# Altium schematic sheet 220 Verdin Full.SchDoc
size A3; Organization: Toradex Solutions Inc.; Address1: 6415 Northwest Drive; Address2: Mississauga, ON, L4V 1X1; Address3: Canada
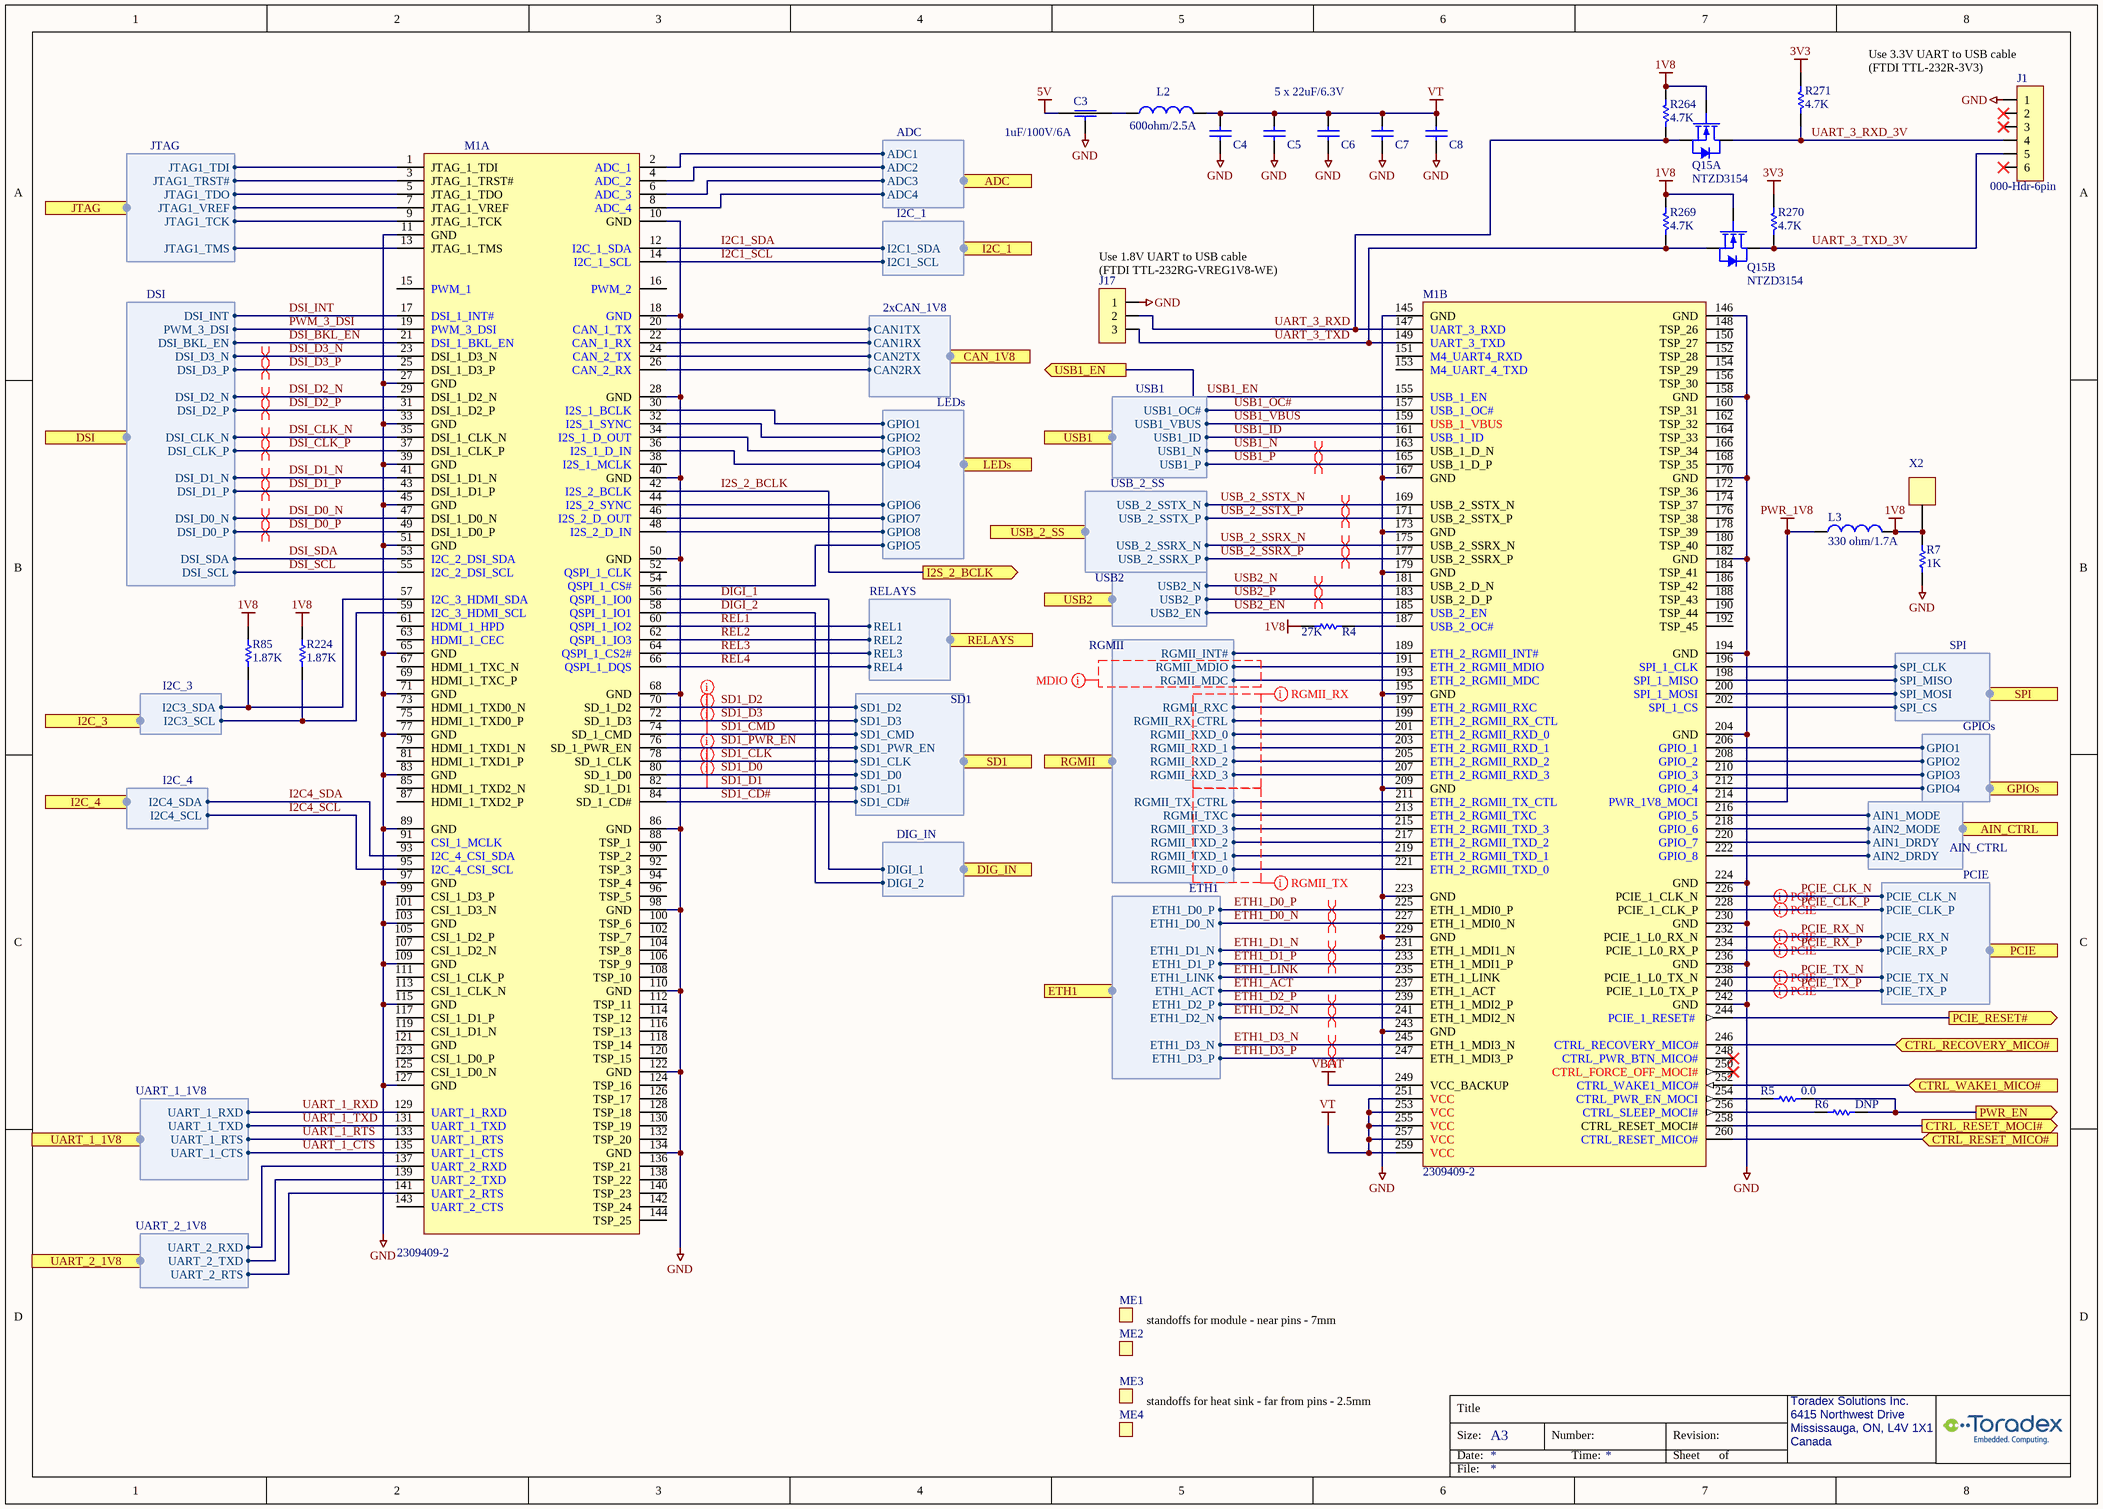
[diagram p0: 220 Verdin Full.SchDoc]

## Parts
C3  value 1uF/100V/6A  [C/1206_3P]  (hidden comment: 0753-Cap 3P-1206-1uF/100V/6A)
C4  22uF/6.3V  [C0402_CAPC1005L]  (value not drawn)
C5  22uF/6.3V  [C0402_CAPC1005L]  (value not drawn)
C6  22uF/6.3V  [C0402_CAPC1005L]  (value not drawn)
C7  22uF/6.3V  [C0402_CAPC1005L]  (value not drawn)
C8  22uF/6.3V  [C0402_CAPC1005L]  (value not drawn)
J1  000-Hdr-6pin  [HDR1X6]
J17  000-Hdr-3pin  [HDR1X3]  (value not drawn)
L2  value 600ohm/2.5A  [INDP1206]  (hidden comment: 1641-Fer-1206-600ohm/2.5A)
L3  value 330 ohm/1.7A  [INDC1608x095]  (hidden comment: 0405-Fer-0603-330ohm/1.7A)
M1  2309409-2  [CON-TE-2309409-2_TORADEX_VERDIN_MTG_rev2]  (parts A,B of 2)
ME1  9774070243R  [MTG_POST WURTH 774070243]  (value not drawn)
ME2  9774070243R  [MTG_POST WURTH 774070243]  (value not drawn)
ME3  9774025243R  [WURTH_9774025243R]  (value not drawn)
ME4  9774025243R  [WURTH_9774025243R]  (value not drawn)
Q15  NTZD3154  [SOT563]  (parts A,B of 2)
R4  value 27K  [R0402_RESC1005L]  (hidden comment: 1538-Res-0402-27k)
R5  value 0.0  [R/0603]  (hidden comment: 0195-Res-0603-0.0ohm)
R6  value DNP  [R/0603]  (hidden comment: 0000-Res-0603-DNP)
R7  value 1K  [R0402_RESC1005L]  (hidden comment: 1650-Res-0402-1K)
R85  value 1.87K  [R0402_RESC1005L]  (hidden comment: 1536-Res-0402-1.87K)
R224  value 1.87K  [R0402_RESC1005L]  (hidden comment: 1536-Res-0402-1.87K)
R264  value 4.7K  [R0402_RESC1005L]  (hidden comment: 2233-Res-0402-4.7K)
R269  value 4.7K  [R0402_RESC1005L]  (hidden comment: 2233-Res-0402-4.7K)
R270  value 4.7K  [R0402_RESC1005L]  (hidden comment: 2233-Res-0402-4.7K)
R271  value 4.7K  [R0402_RESC1005L]  (hidden comment: 2233-Res-0402-4.7K)
X2  000-TestPoint  [TestPoint_1]  (value not drawn)

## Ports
ADC (harness ADC), AIN_CTRL (harness AIN_CTRL), CAN_1V8 (harness 2xCAN_1V8), CTRL_RECOVERY_MICO# (in), CTRL_RESET_MICO# (in), CTRL_RESET_MOCI# (out), CTRL_WAKE1_MICO# (in), DIG_IN (harness DIG_IN), DSI (harness DSI), ETH1 (harness ETH1), GPIOs (harness GPIOs), I2C_1 (harness I2C_1), I2C_3 (harness I2C_3), I2C_4 (harness I2C_4), I2S_2_BCLK (out), JTAG (harness JTAG), LEDs (harness LEDs), PCIE (harness PCIe), PCIE_RESET# (out), PWR_EN (out), RELAYS (harness RELAYS), RGMII (harness RGMII), SD1 (harness SD1), SPI (harness SPI), UART_1_1V8 (harness UART_1_1V8), UART_2_1V8 (harness UART_2_1V8), USB1 (harness USB1), USB1_EN (out), USB2 (harness USB2), USB_2_SS (harness USB_2_SS)

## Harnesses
ETH1: ETH1_D0_P, ETH1_D0_N, ETH1_D1_N, ETH1_D1_P, ETH1_LINK, ETH1_ACT, ETH1_D2_P, ETH1_D2_N, ETH1_D3_N, ETH1_D3_P
USB2: USB2_N, USB2_P, USB2_EN
USB1: USB1_N, USB1_P, USB1_ID, USB1_VBUS, USB1_OC#
PCIE: PCIE_CLK_N, PCIE_CLK_P, PCIE_RX_N, PCIE_RX_P, PCIE_TX_N, PCIE_TX_P
SPI: SPI_CLK, SPI_MISO, SPI_MOSI, SPI_CS
AIN_CTRL: AIN1_MODE, AIN2_MODE, AIN1_DRDY, AIN2_DRDY
GPIOs: GPIO1, GPIO2, GPIO3, GPIO4
RGMII: RGMII_TXD_0, RGMII_TXD_1, RGMII_TXD_2, RGMII_TXD_3, RGMII_TXC, RGMII_TX_CTRL, RGMII_RXD_0, RGMII_RXD_1, RGMII_RXD_2, RGMII_RXD_3, RGMII_RXC, RGMII_RX_CTRL, RGMII_MDIO, RGMII_MDC, RGMII_INT#
SD1: SD1_D2, SD1_D3, SD1_CMD, SD1_PWR_EN, SD1_CLK, SD1_D0, SD1_D1, SD1_CD#
2xCAN_1V8: CAN1TX, CAN1RX, CAN2TX, CAN2RX
UART_1_1V8: UART_1_RXD, UART_1_TXD, UART_1_RTS, UART_1_CTS
UART_2_1V8: UART_2_RXD, UART_2_TXD, UART_2_RTS
RELAYS: REL1, REL2, REL3, REL4
I2C_1: I2C1_SDA, I2C1_SCL
DIG_IN: DIGI_1, DIGI_2
JTAG: JTAG1_TDI, JTAG1_TRST#, JTAG1_TDO, JTAG1_VREF, JTAG1_TCK, JTAG1_TMS
LEDs: GPIO1, GPIO2, GPIO3, GPIO4, GPIO7, GPIO8, GPIO6, GPIO5
I2C_4: I2C4_SDA, I2C4_SCL
DSI: DSI_SDA, DSI_SCL, DSI_BKL_EN, PWM_3_DSI, DSI_INT, DSI_D3_N, DSI_D3_P, DSI_D2_N, DSI_D2_P, DSI_CLK_N, DSI_CLK_P, DSI_D1_N, DSI_D1_P, DSI_D0_N, DSI_D0_P
ADC: ADC1, ADC2, ADC3, ADC4
I2C_3: I2C3_SDA, I2C3_SCL
USB_2_SS: USB_2_SSTX_N, USB_2_SSTX_P, USB_2_SSRX_N, USB_2_SSRX_P

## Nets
1V8: L3.1 Q15.2(G) Q15.5(G) R4.1 R7.2 R85.2 R224.2 R264.1 R269.1 X2.1
3V3: R270.1 R271.1
5V: C3.1(In/Out)
GND: C3.2(Gnd) C4.1 C5.1 C6.1 C7.1 C8.1 J1.1 J17.1 M1.10(GND) M1.11(GND) M1.18(GND) M1.27(GND) M1.28(GND) M1.33(GND) M1.39(GND) M1.40(GND) M1.45(GND) M1.50(GND) M1.51(GND) M1.65(GND) M1.68(GND) M1.71(GND) M1.77(GND) M1.83(GND) M1.86(GND) M1.89(GND) M1.97(GND) M1.98(GND) M1.103(GND) M1.109(GND) M1.110(GND) M1.115(GND) M1.122(GND) M1.127(GND) M1.134(GND) M1.145(GND) M1.146(GND) M1.158(GND) M1.167(GND) M1.170(GND) M1.173(GND) M1.179(GND) M1.182(GND) M1.194(GND) M1.195(GND) M1.204(GND) M1.209(GND) M1.223(GND) M1.224(GND) M1.229(GND) M1.230(GND) M1.236(GND) M1.242(GND) M1.243(GND) R7.1
PWR_1V8: L3.2 M1.214(PWR_1V8_MOCI)
VBAT: M1.249(VCC_BACKUP)
VT: C4.2 C5.2 C6.2 C7.2 C8.2 L2.2 M1.251(VCC) M1.253(VCC) M1.255(VCC) M1.257(VCC) M1.259(VCC)
CTRL_RECOVERY_MICO#: M1.246(CTRL_RECOVERY_MICO#) ; port CTRL_RECOVERY_MICO#
CTRL_RESET_MICO#: M1.260(CTRL_RESET_MICO#) ; port CTRL_RESET_MICO#
CTRL_RESET_MOCI#: M1.258(CTRL_RESET_MOCI#) ; port CTRL_RESET_MOCI#
CTRL_WAKE1_MICO#: M1.252(CTRL_WAKE1_MICO#) ; port CTRL_WAKE1_MICO#
DIGI_1: M1.56(QSPI_1_IO0) ; port DIG_IN.DIGI_1
DIGI_2: M1.58(QSPI_1_IO1) ; port DIG_IN.DIGI_2
DSI_BKL_EN: M1.21(DSI_1_BKL_EN) ; port DSI.DSI_BKL_EN
DSI_CLK_N: M1.35(DSI_1_CLK_N) ; port DSI.DSI_CLK_N
DSI_CLK_P: M1.37(DSI_1_CLK_P) ; port DSI.DSI_CLK_P
DSI_D0_N: M1.47(DSI_1_D0_N) ; port DSI.DSI_D0_N
DSI_D0_P: M1.49(DSI_1_D0_P) ; port DSI.DSI_D0_P
DSI_D1_N: M1.41(DSI_1_D1_N) ; port DSI.DSI_D1_N
DSI_D1_P: M1.43(DSI_1_D1_P) ; port DSI.DSI_D1_P
DSI_D2_N: M1.29(DSI_1_D2_N) ; port DSI.DSI_D2_N
DSI_D2_P: M1.31(DSI_1_D2_P) ; port DSI.DSI_D2_P
DSI_D3_N: M1.23(DSI_1_D3_N) ; port DSI.DSI_D3_N
DSI_D3_P: M1.25(DSI_1_D3_P) ; port DSI.DSI_D3_P
DSI_INT: M1.17(DSI_1_INT#) ; port DSI.DSI_INT
DSI_SCL: M1.55(I2C_2_DSI_SCL) ; port DSI.DSI_SCL
DSI_SDA: M1.53(I2C_2_DSI_SDA) ; port DSI.DSI_SDA
ETH1_ACT: M1.237(ETH_1_ACT) ; port ETH1.ETH1_ACT
ETH1_D0_N: M1.227(ETH_1_MDI0_N) ; port ETH1.ETH1_D0_N
ETH1_D0_P: M1.225(ETH_1_MDI0_P) ; port ETH1.ETH1_D0_P
ETH1_D1_N: M1.231(ETH_1_MDI1_N) ; port ETH1.ETH1_D1_N
ETH1_D1_P: M1.233(ETH_1_MDI1_P) ; port ETH1.ETH1_D1_P
ETH1_D2_N: M1.241(ETH_1_MDI2_N) ; port ETH1.ETH1_D2_N
ETH1_D2_P: M1.239(ETH_1_MDI2_P) ; port ETH1.ETH1_D2_P
ETH1_D3_N: M1.245(ETH_1_MDI3_N) ; port ETH1.ETH1_D3_N
ETH1_D3_P: M1.247(ETH_1_MDI3_P) ; port ETH1.ETH1_D3_P
ETH1_LINK: M1.235(ETH_1_LINK) ; port ETH1.ETH1_LINK
I2C1_SCL: M1.14(I2C_1_SCL) ; port I2C_1.I2C1_SCL
I2C1_SDA: M1.12(I2C_1_SDA) ; port I2C_1.I2C1_SDA
I2C4_SCL: M1.95(I2C_4_CSI_SCL) ; port I2C_4.I2C4_SCL
I2C4_SDA: M1.93(I2C_4_CSI_SDA) ; port I2C_4.I2C4_SDA
I2S_2_BCLK: M1.42(I2S_2_BCLK) ; port I2S_2_BCLK
PCIE_CLK_N: M1.226(PCIE_1_CLK_N) ; port PCIE.PCIE_CLK_N
PCIE_CLK_P: M1.228(PCIE_1_CLK_P) ; port PCIE.PCIE_CLK_P
PCIE_RESET#: M1.244(PCIE_1_RESET#) ; port PCIE_RESET#
PCIE_RX_N: M1.232(PCIE_1_L0_RX_N) ; port PCIE.PCIE_RX_N
PCIE_RX_P: M1.234(PCIE_1_L0_RX_P) ; port PCIE.PCIE_RX_P
PCIE_TX_N: M1.238(PCIE_1_L0_TX_N) ; port PCIE.PCIE_TX_N
PCIE_TX_P: M1.240(PCIE_1_L0_TX_P) ; port PCIE.PCIE_TX_P
PWM_3_DSI: M1.19(PWM_3_DSI) ; port DSI.PWM_3_DSI
PWR_EN: R5.1 R6.1 ; port PWR_EN
REL1: M1.60(QSPI_1_IO2) ; port RELAYS.REL1
REL2: M1.62(QSPI_1_IO3) ; port RELAYS.REL2
REL3: M1.64(QSPI_1_CS2#) ; port RELAYS.REL3
REL4: M1.66(QSPI_1_DQS) ; port RELAYS.REL4
SD1_CD#: M1.84(SD_1_CD#) ; port SD1.SD1_CD#
SD1_CLK: M1.78(SD_1_CLK) ; port SD1.SD1_CLK
SD1_CMD: M1.74(SD_1_CMD) ; port SD1.SD1_CMD
SD1_D0: M1.80(SD_1_D0) ; port SD1.SD1_D0
SD1_D1: M1.82(SD_1_D1) ; port SD1.SD1_D1
SD1_D2: M1.70(SD_1_D2) ; port SD1.SD1_D2
SD1_D3: M1.72(SD_1_D3) ; port SD1.SD1_D3
SD1_PWR_EN: M1.76(SD_1_PWR_EN) ; port SD1.SD1_PWR_EN
UART_1_CTS: M1.135(UART_1_CTS) ; port UART_1_1V8.UART_1_CTS
UART_1_RTS: M1.133(UART_1_RTS) ; port UART_1_1V8.UART_1_RTS
UART_1_RXD: M1.129(UART_1_RXD) ; port UART_1_1V8.UART_1_RXD
UART_1_TXD: M1.131(UART_1_TXD) ; port UART_1_1V8.UART_1_TXD
UART_3_RXD: J17.2 M1.147(UART_3_RXD) Q15.1(S) R264.2
UART_3_RXD_3V: J1.4 Q15.6(D) R271.2
UART_3_TXD: J17.3 M1.149(UART_3_TXD) Q15.4(S) R269.2
UART_3_TXD_3V: J1.5 Q15.3(D) R270.2
USB1_EN: M1.155(USB_1_EN) ; port USB1_EN
USB1_ID: M1.161(USB_1_ID) ; port USB1.USB1_ID
USB1_N: M1.163(USB_1_D_N) ; port USB1.USB1_N
USB1_OC#: M1.157(USB_1_OC#) ; port USB1.USB1_OC#
USB1_P: M1.165(USB_1_D_P) ; port USB1.USB1_P
USB1_VBUS: M1.159(USB_1_VBUS) ; port USB1.USB1_VBUS
USB2_EN: M1.185(USB_2_EN) ; port USB2.USB2_EN
USB2_N: M1.181(USB_2_D_N) ; port USB2.USB2_N
USB2_P: M1.183(USB_2_D_P) ; port USB2.USB2_P
USB_2_SSRX_N: M1.175(USB_2_SSRX_N) ; port USB_2_SS.USB_2_SSRX_N
USB_2_SSRX_P: M1.177(USB_2_SSRX_P) ; port USB_2_SS.USB_2_SSRX_P
USB_2_SSTX_N: M1.169(USB_2_SSTX_N) ; port USB_2_SS.USB_2_SSTX_N
USB_2_SSTX_P: M1.171(USB_2_SSTX_P) ; port USB_2_SS.USB_2_SSTX_P
NetC3_3: C3.3(In/Out) L2.1
NetM1_1: M1.1(JTAG_1_TDI) ; port JTAG.JTAG1_TDI
NetM1_2: M1.2(ADC_1) ; port ADC.ADC1
NetM1_3: M1.3(JTAG_1_TRST#) ; port JTAG.JTAG1_TRST#
NetM1_4: M1.4(ADC_2) ; port ADC.ADC2
NetM1_5: M1.5(JTAG_1_TDO) ; port JTAG.JTAG1_TDO
NetM1_6: M1.6(ADC_3) ; port ADC.ADC3
NetM1_7: M1.7(JTAG_1_VREF) ; port JTAG.JTAG1_VREF
NetM1_8: M1.8(ADC_4) ; port ADC.ADC4
NetM1_9: M1.9(JTAG_1_TCK) ; port JTAG.JTAG1_TCK
NetM1_13: M1.13(JTAG_1_TMS) ; port JTAG.JTAG1_TMS
NetM1_20: M1.20(CAN_1_TX) ; port CAN_1V8.CAN1TX
NetM1_22: M1.22(CAN_1_RX) ; port CAN_1V8.CAN1RX
NetM1_24: M1.24(CAN_2_TX) ; port CAN_1V8.CAN2TX
NetM1_26: M1.26(CAN_2_RX) ; port CAN_1V8.CAN2RX
NetM1_30: M1.30(I2S_1_BCLK) ; port LEDs.GPIO1
NetM1_32: M1.32(I2S_1_SYNC) ; port LEDs.GPIO2
NetM1_34: M1.34(I2S_1_D_OUT) ; port LEDs.GPIO3
NetM1_36: M1.36(I2S_1_D_IN) ; port LEDs.GPIO4
NetM1_44: M1.44(I2S_2_SYNC) ; port LEDs.GPIO6
NetM1_46: M1.46(I2S_2_D_OUT) ; port LEDs.GPIO7
NetM1_48: M1.48(I2S_2_D_IN) ; port LEDs.GPIO8
NetM1_54: M1.54(QSPI_1_CS#) ; port LEDs.GPIO5
NetM1_57: M1.57(I2C_3_HDMI_SDA) R85.1 ; port I2C_3.I2C3_SDA
NetM1_59: M1.59(I2C_3_HDMI_SCL) R224.1 ; port I2C_3.I2C3_SCL
NetM1_137: M1.137(UART_2_RXD) ; port UART_2_1V8.UART_2_RXD
NetM1_139: M1.139(UART_2_TXD) ; port UART_2_1V8.UART_2_TXD
NetM1_141: M1.141(UART_2_RTS) ; port UART_2_1V8.UART_2_RTS
NetM1_187: M1.187(USB_2_OC#) R4.2
NetM1_189: M1.189(ETH_2_RGMII_INT#) ; port RGMII.RGMII_INT#
NetM1_191: M1.191(ETH_2_RGMII_MDIO) ; port RGMII.RGMII_MDIO
NetM1_193: M1.193(ETH_2_RGMII_MDC) ; port RGMII.RGMII_MDC
NetM1_196: M1.196(SPI_1_CLK) ; port SPI.SPI_CLK
NetM1_197: M1.197(ETH_2_RGMII_RXC) ; port RGMII.RGMII_RXC
NetM1_198: M1.198(SPI_1_MISO) ; port SPI.SPI_MISO
NetM1_199: M1.199(ETH_2_RGMII_RX_CTL) ; port RGMII.RGMII_RX_CTRL
NetM1_200: M1.200(SPI_1_MOSI) ; port SPI.SPI_MOSI
NetM1_201: M1.201(ETH_2_RGMII_RXD_0) ; port RGMII.RGMII_RXD_0
NetM1_202: M1.202(SPI_1_CS) ; port SPI.SPI_CS
NetM1_203: M1.203(ETH_2_RGMII_RXD_1) ; port RGMII.RGMII_RXD_1
NetM1_205: M1.205(ETH_2_RGMII_RXD_2) ; port RGMII.RGMII_RXD_2
NetM1_206: M1.206(GPIO_1) ; port GPIOs.GPIO1
NetM1_207: M1.207(ETH_2_RGMII_RXD_3) ; port RGMII.RGMII_RXD_3
NetM1_208: M1.208(GPIO_2) ; port GPIOs.GPIO2
NetM1_210: M1.210(GPIO_3) ; port GPIOs.GPIO3
NetM1_211: M1.211(ETH_2_RGMII_TX_CTL) ; port RGMII.RGMII_TX_CTRL
NetM1_212: M1.212(GPIO_4) ; port GPIOs.GPIO4
NetM1_213: M1.213(ETH_2_RGMII_TXC) ; port RGMII.RGMII_TXC
NetM1_215: M1.215(ETH_2_RGMII_TXD_3) ; port RGMII.RGMII_TXD_3
NetM1_216: M1.216(GPIO_5) ; port AIN_CTRL.AIN1_MODE
NetM1_217: M1.217(ETH_2_RGMII_TXD_2) ; port RGMII.RGMII_TXD_2
NetM1_218: M1.218(GPIO_6) ; port AIN_CTRL.AIN2_MODE
NetM1_219: M1.219(ETH_2_RGMII_TXD_1) ; port RGMII.RGMII_TXD_1
NetM1_220: M1.220(GPIO_7) ; port AIN_CTRL.AIN1_DRDY
NetM1_221: M1.221(ETH_2_RGMII_TXD_0) ; port RGMII.RGMII_TXD_0
NetM1_222: M1.222(GPIO_8) ; port AIN_CTRL.AIN2_DRDY
NetM1_254: M1.254(CTRL_PWR_EN_MOCI) R5.2
NetM1_256: M1.256(CTRL_SLEEP_MOCI#) R6.2

Not connected (* = marked no-connect by the designer): J1 2* 3* 6*; M1 15(PWM_1) 16(PWM_2) 38(I2S_1_MCLK) 52(QSPI_1_CLK) 61(HDMI_1_HPD) 63(HDMI_1_CEC) 67(HDMI_1_TXC_N) 69(HDMI_1_TXC_P) 73(HDMI_1_TXD0_N) 75(HDMI_1_TXD0_P) 79(HDMI_1_TXD1_N) 81(HDMI_1_TXD1_P) 85(HDMI_1_TXD2_N) 87(HDMI_1_TXD2_P) 88(TSP_1) 90(TSP_2) 91(CSI_1_MCLK) 92(TSP_3) 94(TSP_4) 96(TSP_5) 99(CSI_1_D3_P) 100(TSP_6) 101(CSI_1_D3_N) 102(TSP_7) 104(TSP_8) 105(CSI_1_D2_P) 106(TSP_9) 107(CSI_1_D2_N) 108(TSP_10) 111(CSI_1_CLK_P) 112(TSP_11) 113(CSI_1_CLK_N) 114(TSP_12) 116(TSP_13) 117(CSI_1_D1_P) 118(TSP_14) 119(CSI_1_D1_N) 120(TSP_15) 121(GND) 123(CSI_1_D0_P) 124(TSP_16) 125(CSI_1_D0_N) 126(TSP_17) 128(TSP_18) 130(TSP_19) 132(TSP_20) 136(TSP_21) 138(TSP_22) 140(TSP_23) 142(TSP_24) 143(UART_2_CTS) 144(TSP_25) 148(TSP_26) 150(TSP_27) 151(M4_UART4_RXD) 152(TSP_28) 153(M4_UART_4_TXD) 154(TSP_29) 156(TSP_30) 160(TSP_31) 162(TSP_32) 164(TSP_33) 166(TSP_34) 168(TSP_35) 172(TSP_36) 174(TSP_37) 176(TSP_38) 178(TSP_39) 180(TSP_40) 184(TSP_41) 186(TSP_42) 188(TSP_43) 190(TSP_44) 192(TSP_45) 248(CTRL_PWR_BTN_MICO#)* 250(CTRL_FORCE_OFF_MOCI#)*

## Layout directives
differential pair; differential pair class PCIE: PCIE_CLK_N, PCIE_CLK_P, PCIE_RX_N, PCIE_RX_P, PCIE_TX_N, PCIE_TX_P
differential pair; differential pair class ETH1: ETH1_D0_N, ETH1_D0_P, ETH1_D1_N, ETH1_D1_P, ETH1_D2_N, ETH1_D2_P, ETH1_D3_N, ETH1_D3_P
differential pair; differential pair class USB2; differential pair class USB: USB2_N, USB2_P
differential pair; differential pair class USB1; differential pair class USB: USB1_N, USB1_P
net class SD1: SD1_CLK, SD1_CMD, SD1_D0, SD1_D1, SD1_D2, SD1_D3
differential pair; differential pair class DSI: DSI_CLK_N, DSI_CLK_P, DSI_D0_N, DSI_D0_P, DSI_D1_N, DSI_D1_P, DSI_D2_N, DSI_D2_P, DSI_D3_N, DSI_D3_P
net class MDIO: (no net found under the mark)
net class RGMII_RX: (no net found under the mark)
net class RGMII_TX: (no net found under the mark)
differential pair; differential pair class USB2_SS; differential pair class USB: USB_2_SSRX_N, USB_2_SSRX_P, USB_2_SSTX_N, USB_2_SSTX_P

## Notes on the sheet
- 5 x 22uF/6.3V
- (near J1) Use 3.3V UART to USB cable
  (FTDI TTL-232R-3V3)
- (near J17) Use 1.8V UART to USB cable
  (FTDI TTL-232RG-VREG1V8-WE)
- standoffs for module - near pins - 7mm
- standoffs for heat sink - far from pins - 2.5mm

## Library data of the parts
C3 = 0753-Cap 3P-1206-1uF/100V/6A: (-55 to 125 DegC) CAP FEEDTHRU 1UF 20% 100V 1206 6A; Mfr: TDK Corporation; MfrNo: YFF31HC2A105MT000N; PN: 753; Alt: YFF31AH2A105MT0Y0N
C4-C8 = 2404-Cap-0402-22uF/6.3V: (-55 to 85 DegC) CAP CER 22UF 6.3V 20% X5R 0402; MfrNo: GRM155R60J226ME11D; Mfr: Murata; PN: 2404
J1 = 000-Hdr-6pin: Header, 6-Pin; Note: PCB footprint only, no parts to buy or assemble
J17 = 000-Hdr-3pin: Header, 3-Pin; Note: PCB footprint only, no parts to buy or assemble
L2 = 1641-Fer-1206-600ohm/2.5A: (-55 to 125 DegC AEC) FERRITE BEAD 600ohm 1206 2.5A 50mohm R@1A@150MHz:40.7ohm; Mfr: Wurth Electronics; MfrNo: 78279221601; PN: 1641; Notes: similar performance for 1A@150MHz: 742792116, 742792121, 782763301
L3 = 0405-Fer-0603-330ohm/1.7A: (-55 to 125 DegC) FERRITE BEAD 330 OHM 0603 1.7A 80mohm, typ 48mohm; Mfr: TDK Corporation; MfrNo: MPZ1608S331ATA00; PN: 405; TR: 445-5221-2-ND; DR: 445-5221-6-ND; DR2: 810-MPZ1608S331ATA00
M1 = 1140-Conn-Toradex-Verdin: (-55 to 85 DegC) CONN DDR4 SODIMM 260P 5.2H STD; Mfr: TE Connectivity; PN: 1140
ME1 ME2 = 1412-Post-M2-7mm: (-55 to 155 DegC) ROUND STANDOFF M2X0.4 STEEL 7MM for Verdin; Mfr: Wurth Electronics; PN: 1412
ME3 ME4 = 1141-Post-M2-2.5mm: (-55 to 155 DegC) ROUND STANDOFF M2X0.4 STEEL 2.5MM for Verdin; Mfr: Wurth Electronics; PN: 1141
Q15 = 1146-NTZD3154NT1G: (-55 to 150 DegC) MOSFET 2N-CH (dual) 20V 0.54A SOT-563 1.6x1.6mm Vth:1V Ron typ:400m@4.5V, 500m@2.5V, 700m@1.8V; Mfr: ON Semiconductor; PN: 1146; Alt: NTZD3154NT5G,PMDT290UNE,115
R4 = 1538-Res-0402-27k: (-55 to 155 DegC AEC) RES 27K OHM 1% 1/16W 100ppm 0402; Mfr: Stackpole Electronics; MfrNo: RMCF0402FT27K0; PN: 1538; Alt: AC0402FR-0727KL,CRGCQ0402F27K
R5 = 0195-Res-0603-0.0ohm: (-55 to 155 DegC) RES 0.0 OHM 1/10W JUMP 0603; Mfr: Samsung; MfrNo: RC1608J000CS; Alt: 311-0.0GRCT-ND; Alt2: A106051CT-ND; PN: 195; TR: 1276-3510-2-ND
R6 = 0000-Res-0603-DNP: RES 0603
R7 = 1650-Res-0402-1K: (-55 to 155 DegC AEC) RES 1K OHM 1% 1/16W 100ppm 0402; MfrNo: CRGCQ0402F1K0; Mfr: TE Connectivity; Alt: CR0402AFX-1001GLF,AC0402FR-131KL,AC0402FR-071KL; PN: 1650
R85 R224 = 1536-Res-0402-1.87K: (-55 to 155 DegC AEC) RES 1.87K OHM 1% 1/16W 100ppm 0402; MfrNo: RMCF0402FT1K87; Mfr: Stackpole Electronics; Alt: AC0402FR-071K87L,RK73H1ETTP1871F,ERJ-2RKF1871X; PN: 1536
R264 R269-R271 = 2233-Res-0402-4.7K: (-55 to 155 DegC) RES 4.70K OHM 1/16W 1% 0402 100ppm; MfrNo: RC0402FR-074K7L; Mfr: Yageo; PN: 2233
X2 = 000-TestPoint: Note: this is PCB footprint only, no parts to buy or assemble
